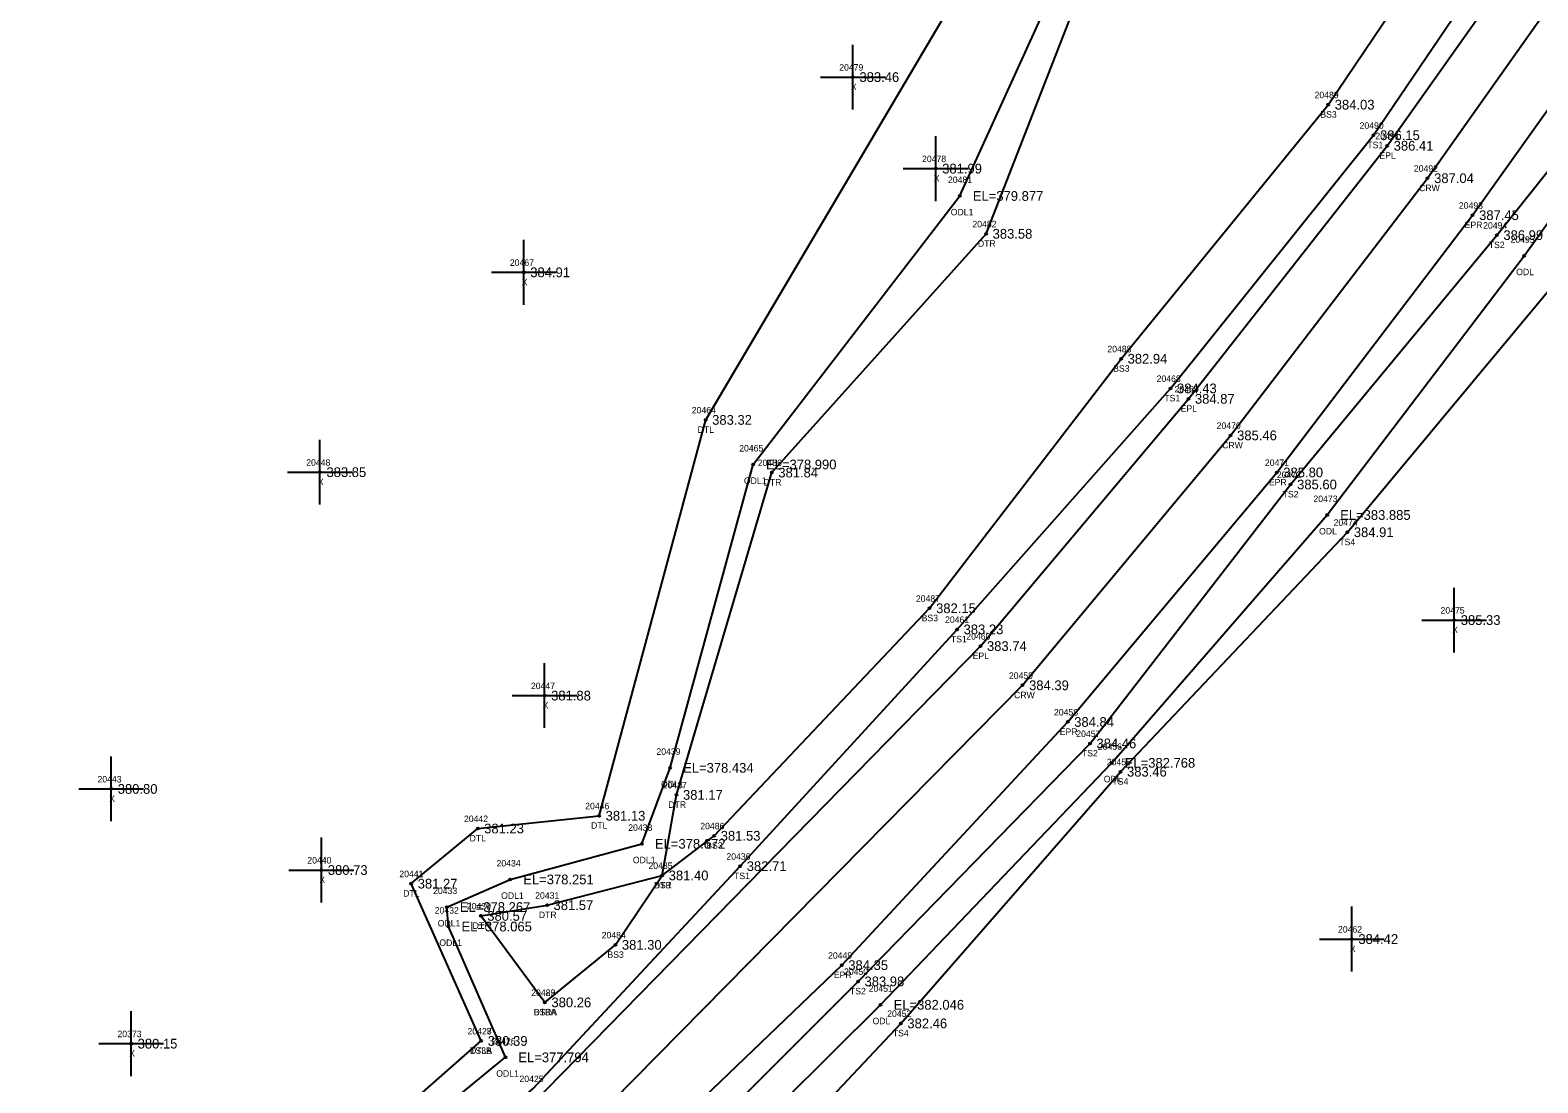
# Model space of a CAD drawing. Extents: x 2116373 to 2118139, y 979529 to 981026.
# Drawn here: x 2117652.3 to 2117884.9, y 980505.4 to 980667.9 of the extents above; entities that cross this region are included whole.
import ezdxf

# ---------------------------------------------------------------- set-up
doc = ezdxf.new("R2010")
doc.units = 0
for name, color, linetype in [('RD_DTM_BkLn1', 7, 'Continuous'), ('RD_DTM_BkLn2', 7, 'Continuous'), ('RD_DTM_BkLn_txCode', 7, 'Continuous'), ('RD_EX_H2O', 7, 'Continuous'), ('RD_EX_H2O_txCode', 7, 'Continuous'), ('RD_EX_Misc', 7, 'Continuous'), ('RD_EX_Misc_txCode', 7, 'Continuous'), ('RD_EX_Road', 7, 'Continuous'), ('RD_EX_Road_txCode', 7, 'Continuous'), ('RD_EX_TX_H2O_ELEV', 7, 'Continuous'), ('RD_EX_TX_Misc_ELEV', 7, 'Continuous'), ('RD_EX_TX_Road_ELEV', 7, 'Continuous'), ('RD_HC_Survey_ELEV', 7, 'Continuous'), ('RD_HC_Survey_txCode', 7, 'Continuous'), ('RD_SMD_Locator', 7, 'Continuous')]:
    doc.layers.add(name, color=color, linetype=linetype)

msp = doc.modelspace()

# ---------------------------------------------------------------- linework, layer by layer
at = {"layer": 'RD_DTM_BkLn1'}
msp.add_lwpolyline([(2117394.63, 980185.41), (2117475.35, 980259.39), (2117549.63, 980326.58), (2117623.5, 980394.2), (2117697.55, 980461.75), (2117735.02, 980495.39), (2117805.43, 980566.78), (2117837.53, 980605.36), (2117867.93, 980645.06), (2117897.09, 980686.34), (2117923.66, 980727.51), (2117948.72, 980771.39), (2117971.22, 980818.34), (2117988.96, 980866.05), (2117991.42, 980873.14), (2118004.26, 980915.09), (2118016.82, 980963.49), (2118028.02, 981013.26)], dxfattribs=at)
at = {"layer": 'RD_DTM_BkLn2'}
for points in [[(2117493.39, 980317.39), (2117496.3, 980311.64), (2117501.39, 980308.35), (2117540.21, 980337.44), (2117614.76, 980403.8), (2117689.51, 980469.61), (2117729.91, 980504.53), (2117761.86, 980538.86), (2117795.32, 980575.41), (2117828.25, 980612.61), (2117859.59, 980651.69), (2117887.1, 980692.35), (2117913.78, 980733.2), (2117937.24, 980777.08), (2117959.23, 980820.82), (2117978.84, 980869.89), (2117994.26, 980920.18), (2118007.51, 980964.57), (2118017.18, 981016.23)], [(2117731.72, 980517.83), (2117742.59, 980526.71), (2117749.81, 980537.43), (2117757.84, 980543.55), (2117791.08, 980578.67), (2117820.63, 980617.19), (2117852.6, 980656.41), (2117879.28, 980696.02), (2117905.09, 980736.34), (2117929.71, 980780.7), (2117946.34, 980825.73), (2117956.18, 980836.51)], [(2117403.18, 980177.15), (2117405.35, 980174.66), (2117487.26, 980245.43), (2117563.99, 980312.17), (2117634.65, 980381.46), (2117704.3, 980451.46), (2117722.65, 980465.11), (2117743.87, 980484.9), (2117780.03, 980521.07), (2117815.83, 980557.8), (2117846.79, 980597.78), (2117878.62, 980636.27), (2117911.26, 980677.34), (2117934.7, 980720.41), (2117959.82, 980759.29), (2117971.51, 980778.31), (2117986.8, 980774.26), (2117987.85, 980770.9), (2117995.22, 980745.17), (2118001.26, 980694.98), (2118008.4, 980640.04)], [(2117734.28, 980458.87), (2117786.65, 980514.59), (2117820.54, 980553.44), (2117855.54, 980590.41), (2117887.71, 980629.08), (2117918.16, 980671.7), (2117943.36, 980714.4), (2117971.9, 980758.61), (2117977.71, 980769.98), (2117980.03, 980767.32), (2117984.46, 980744.95), (2117988.75, 980693.43), (2117998.28, 980638.86)], [(2117660.7, 980455.28), (2117683.5, 980478.1), (2117721.89, 980511.88)]]:
    msp.add_lwpolyline(points, dxfattribs=at)
at = {"layer": 'RD_EX_H2O'}
for points in [[(2117721.89, 980511.88), (2117711.08, 980536.16), (2117721.34, 980544.67), (2117740.08, 980546.64), (2117756.52, 980607.75), (2117807.52, 980694.09), (2117832.51, 980780.02), (2117861.02, 980821.18)], [(2117660.7, 980455.28), (2117684.91, 980475.95), (2117725.61, 980509.35), (2117716.83, 980529.54), (2117716.58, 980532.55), (2117726.37, 980536.81), (2117746.69, 980542.31), (2117751.04, 980554.04), (2117763.83, 980600.87), (2117795.75, 980642.32), (2117816.16, 980687.22), (2117820.4, 980726.27), (2117839.5, 980777.36), (2117872.08, 980815.27)], [(2117731.72, 980517.83), (2117721.82, 980531.18), (2117732.04, 980532.84), (2117749.81, 980537.43), (2117752.02, 980549.86), (2117766.73, 980599.62), (2117799.8, 980636.48), (2117820.1, 980688.63), (2117829.93, 980722.05), (2117843.24, 980773.85), (2117874.6, 980813.55)], [(2117725.24, 980456.84), (2117729.88, 980462.23), (2117745.69, 980479.89), (2117783.52, 980517.46), (2117819.19, 980554.81), (2117852.43, 980593.07), (2117882.84, 980633.09), (2117913.27, 980675.65), (2117938.84, 980717.37), (2117963.41, 980761.5), (2117973.8, 980774.7), (2117982.58, 980769.22), (2117983.22, 980768.54), (2117990.51, 980745.52), (2117996.79, 980694.22), (2118004.21, 980639.35)]]:
    msp.add_lwpolyline(points, dxfattribs=at)
at = {"layer": 'RD_EX_Misc'}
for p, q in [((2117779.25, 980655.67), (2117779.25, 980665.67)), ((2117774.25, 980660.67), (2117784.25, 980660.67)), ((2117792.02, 980641.54), (2117792.02, 980651.54)), ((2117787.02, 980646.54), (2117797.02, 980646.54)), ((2117728.45, 980625.53), (2117728.45, 980635.53)), ((2117723.45, 980630.53), (2117733.45, 980630.53)), ((2117697, 980594.68), (2117697, 980604.68)), ((2117692, 980599.68), (2117702, 980599.68)), ((2117872.04, 980571.85), (2117872.04, 980581.85)), ((2117867.04, 980576.85), (2117877.04, 980576.85)), ((2117731.67, 980560.19), (2117731.67, 980570.19)), ((2117726.67, 980565.19), (2117736.67, 980565.19)), ((2117664.79, 980545.78), (2117664.79, 980555.78)), ((2117659.79, 980550.78), (2117669.79, 980550.78)), ((2117697.21, 980533.26), (2117697.21, 980543.26)), ((2117692.21, 980538.26), (2117702.21, 980538.26)), ((2117856.24, 980522.61), (2117856.24, 980532.61)), ((2117851.24, 980527.61), (2117861.24, 980527.61)), ((2117667.86, 980506.46), (2117667.86, 980516.46)), ((2117662.86, 980511.46), (2117672.86, 980511.46))]:
    msp.add_line(p, q, dxfattribs=at)
at = {"layer": 'RD_EX_Road'}
for points in [[(2117394.63, 980185.41), (2117388.45, 980192.75), (2117469.76, 980266.25), (2117487.02, 980282.1), (2117515.02, 980307.24), (2117543.53, 980333.04), (2117617.72, 980400.8), (2117691.88, 980468.07), (2117729.57, 980501.96), (2117798.93, 980572.83), (2117831.02, 980611), (2117861.69, 980650.07), (2117890.37, 980690.61), (2117916.67, 980731.93), (2117941.38, 980774.84), (2117963.75, 980821.95), (2117981.56, 980869.78), (2117996.2, 980917.73), (2118008.9, 980966.42), (2118019.55, 981015.46)], [(2117394.63, 980185.41), (2117401.85, 980177.36), (2117480.62, 980253.04), (2117556.27, 980319.95), (2117629.74, 980387.35), (2117703.2, 980454.29), (2117741.39, 980488.9), (2117777.53, 980523.58), (2117812.39, 980561.12), (2117844.66, 980599.64), (2117874.87, 980639.35), (2117904.78, 980681.4), (2117931.2, 980722.71), (2117957.05, 980767.35), (2117963.67, 980781.11), (2117980.28, 980814.62), (2117994.42, 980851.98)]]:
    msp.add_lwpolyline(points, dxfattribs=at)
at = {"layer": 'RD_SMD_Locator'}
for centre in [(2117779.25, 980660.67), (2117852.6, 980656.41), (2117859.59, 980651.69), (2117861.69, 980650.07), (2117792.02, 980646.54), (2117867.93, 980645.06), (2117795.75, 980642.32), (2117874.87, 980639.35), (2117799.8, 980636.48), (2117878.62, 980636.27), (2117882.84, 980633.09), (2117728.45, 980630.53), (2117820.63, 980617.19), (2117828.25, 980612.61), (2117831.02, 980611), (2117756.52, 980607.75), (2117837.53, 980605.36), (2117763.83, 980600.87), (2117697, 980599.68), (2117766.73, 980599.62), (2117844.66, 980599.64), (2117846.79, 980597.78), (2117852.43, 980593.07), (2117855.54, 980590.41), (2117791.08, 980578.67), (2117872.04, 980576.85), (2117795.32, 980575.41), (2117798.93, 980572.83), (2117731.67, 980565.19), (2117805.43, 980566.78), (2117812.39, 980561.12), (2117815.83, 980557.8), (2117751.04, 980554.04), (2117819.19, 980554.81), (2117820.54, 980553.44), (2117664.79, 980550.78), (2117752.02, 980549.86), (2117740.08, 980546.64), (2117721.34, 980544.67), (2117746.69, 980542.31), (2117757.84, 980543.55), (2117697.21, 980538.26), (2117749.81, 980537.43), (2117749.81, 980537.43), (2117761.86, 980538.86), (2117711.08, 980536.16), (2117726.37, 980536.81), (2117732.04, 980532.84), (2117716.58, 980532.55), (2117721.82, 980531.18), (2117716.83, 980529.54), (2117742.59, 980526.71), (2117856.24, 980527.61), (2117777.53, 980523.58), (2117780.03, 980521.07), (2117731.72, 980517.83), (2117731.72, 980517.83), (2117783.52, 980517.46), (2117786.65, 980514.59), (2117721.89, 980511.88), (2117721.89, 980511.88), (2117667.86, 980511.46), (2117725.61, 980509.35)]:
    msp.add_circle(centre, 0.15, dxfattribs=at)

# ---------------------------------------------------------------- texts
at = {"layer": 'RD_DTM_BkLn_txCode'}
for s, p in [('20489', (2117850.48, 980657.41)), ('BS3', (2117851.37, 980654.41)), ('20490', (2117857.43, 980652.69)), ('TS1', (2117858.63, 980649.69)), ('20494', (2117876.5, 980637.27)), ('TS2', (2117877.37, 980634.27)), ('20488', (2117818.51, 980618.19)), ('BS3', (2117819.4, 980615.19)), ('20468', (2117826.11, 980613.61)), ('TS1', (2117827.29, 980610.61)), ('20472', (2117844.67, 980598.78)), ('TS2', (2117845.55, 980595.78)), ('20474', (2117853.42, 980591.41)), ('TS4', (2117854.3, 980588.41)), ('20487', (2117788.96, 980579.67)), ('BS3', (2117789.85, 980576.67)), ('20461', (2117793.46, 980576.41)), ('TS1', (2117794.36, 980573.41)), ('20457', (2117813.71, 980558.8)), ('TS2', (2117814.59, 980555.8)), ('20455', (2117818.42, 980554.44)), ('TS4', (2117819.29, 980551.44)), ('20486', (2117755.69, 980544.55)), ('BS3', (2117756.61, 980541.55)), ('20436', (2117759.72, 980539.86)), ('20485', (2117747.69, 980538.43)), ('TS1', (2117760.9, 980536.86)), ('BS3', (2117748.58, 980535.43)), ('20484', (2117740.47, 980527.71)), ('BS3', (2117741.36, 980524.71)), ('20450', (2117777.87, 980522.07)), ('20483', (2117729.6, 980518.83)), ('TS2', (2117778.78, 980519.07)), ('BS3A', (2117730, 980515.83)), ('20452', (2117784.53, 980515.59)), ('20427', (2117719.77, 980512.88)), ('TS4', (2117785.4, 980512.59)), ('TS3B', (2117720.17, 980509.88)), ('20425', (2117727.79, 980505.53))]:
    msp.add_text(s, height=1, dxfattribs=at).set_placement(p)
at = {"layer": 'RD_EX_H2O_txCode'}
for s, p in [('20481', (2117793.91, 980644.32)), ('ODL1', (2117794.34, 980639.32)), ('20482', (2117797.68, 980637.48)), ('DTR', (2117798.53, 980634.48)), ('20495', (2117880.72, 980635.09)), ('ODL', (2117881.6, 980630.09)), ('20464', (2117754.38, 980608.75)), ('DTL', (2117755.27, 980605.75)), ('20465', (2117761.69, 980602.87)), ('20466', (2117764.56, 980600.62)), ('ODL1', (2117762.42, 980597.87)), ('DTR', (2117765.46, 980597.62)), ('20473', (2117850.31, 980595.07)), ('ODL', (2117851.18, 980590.07)), ('20439', (2117748.92, 980556.04)), ('20456', (2117817.05, 980556.81)), ('ODL1', (2117749.63, 980551.04)), ('20437', (2117749.9, 980550.86)), ('ODL', (2117817.95, 980551.81)), ('20446', (2117737.93, 980547.64)), ('DTR', (2117750.75, 980547.86)), ('20442', (2117719.22, 980545.67)), ('DTL', (2117738.83, 980544.64)), ('20438', (2117744.57, 980544.31)), ('DTL', (2117720.09, 980542.67)), ('20434', (2117724.25, 980538.81)), ('ODL1', (2117745.28, 980539.31)), ('20441', (2117709.25, 980537.16)), ('20435', (2117747.69, 980538.43)), ('DTL', (2117709.84, 980534.16)), ('20433', (2117714.46, 980534.55)), ('DTR', (2117748.54, 980535.43)), ('20430', (2117719.66, 980532.18)), ('ODL1', (2117724.96, 980533.81)), ('20431', (2117730.21, 980533.84)), ('20432', (2117714.71, 980531.54)), ('ODL1', (2117715.17, 980529.55)), ('DTR', (2117730.77, 980530.84)), ('DTR', (2117720.55, 980529.18)), ('ODL1', (2117715.42, 980526.54)), ('20429', (2117729.6, 980518.83)), ('20451', (2117781.68, 980519.46)), ('DTRA', (2117729.96, 980515.83)), ('ODL', (2117782.27, 980514.46)), ('20428', (2117719.77, 980512.88)), ('20426', (2117723.47, 980511.35)), ('DTLA', (2117720.16, 980509.88)), ('ODL1', (2117724.2, 980506.35))]:
    msp.add_text(s, height=1, dxfattribs=at).set_placement(p)
at = {"layer": 'RD_EX_Misc_txCode'}
for s, p in [('20479', (2117777.13, 980661.67)), ('X', (2117778.93, 980658.67)), ('20478', (2117789.91, 980647.54)), ('X', (2117791.71, 980644.54)), ('20467', (2117726.3, 980631.53)), ('X', (2117728.13, 980628.53)), ('20448', (2117694.88, 980600.68)), ('X', (2117696.68, 980597.68)), ('20475', (2117869.92, 980577.85)), ('X', (2117871.72, 980574.85)), ('20447', (2117729.55, 980566.19)), ('X', (2117731.36, 980563.19)), ('20443', (2117662.67, 980551.78)), ('X', (2117664.47, 980548.78)), ('20440', (2117695.05, 980539.26)), ('X', (2117696.9, 980536.26)), ('20462', (2117854.1, 980528.61)), ('X', (2117855.93, 980525.61)), ('20373', (2117665.75, 980512.46)), ('X', (2117667.55, 980509.46))]:
    msp.add_text(s, height=1, dxfattribs=at).set_placement(p)
at = {"layer": 'RD_EX_Road_txCode'}
for s, p in [('20491', (2117859.86, 980651.07)), ('EPL', (2117860.49, 980648.07)), ('20493', (2117872.75, 980640.35)), ('EPR', (2117873.64, 980637.35)), ('20469', (2117828.88, 980612)), ('EPL', (2117829.82, 980609)), ('20471', (2117842.82, 980600.64)), ('EPR', (2117843.43, 980597.64)), ('20460', (2117796.74, 980573.83)), ('EPL', (2117797.72, 980570.83)), ('20458', (2117810.27, 980562.12)), ('EPR', (2117811.16, 980559.12)), ('20449', (2117775.41, 980524.58)), ('EPR', (2117776.3, 980521.58))]:
    msp.add_text(s, height=1, dxfattribs=at).set_placement(p)
at = {"layer": 'RD_EX_TX_H2O_ELEV'}
for s, p in [('EL=379.877', (2117797.75, 980641.57)), ('383.58', (2117800.8, 980635.73)), ('383.32', (2117757.52, 980607)), ('EL=378.990', (2117765.83, 980600.12)), ('381.84', (2117767.73, 980598.87)), ('EL=383.885', (2117854.43, 980592.32)), ('EL=378.434', (2117753.04, 980553.29)), ('EL=382.768', (2117821.19, 980554.06)), ('381.17', (2117753.02, 980549.11)), ('381.13', (2117741.08, 980545.89)), ('381.23', (2117722.34, 980543.92)), ('EL=378.672', (2117748.69, 980541.56)), ('EL=378.251', (2117728.37, 980536.06)), ('381.40', (2117750.81, 980536.68)), ('381.27', (2117712.08, 980535.41)), ('EL=378.267', (2117718.58, 980531.8)), ('381.57', (2117733.04, 980532.09)), ('380.57', (2117722.82, 980530.43)), ('EL=378.065', (2117718.83, 980528.79)), ('380.26', (2117732.72, 980517.08)), ('EL=382.046', (2117785.52, 980516.71)), ('380.39', (2117722.89, 980511.13)), ('EL=377.794', (2117727.61, 980508.6))]:
    msp.add_text(s, height=1.5, dxfattribs=at).set_placement(p)
at = {"layer": 'RD_EX_TX_Misc_ELEV'}
for s, p in [('383.46', (2117780.25, 980659.92)), ('384.03', (2117853.6, 980655.66)), ('386.15', (2117860.59, 980650.94)), ('381.99', (2117793.02, 980645.79)), ('386.99', (2117879.62, 980635.52)), ('384.91', (2117729.45, 980629.78)), ('382.94', (2117821.63, 980616.44)), ('384.43', (2117829.25, 980611.86)), ('383.85', (2117698, 980598.93)), ('385.60', (2117847.79, 980597.03)), ('384.91', (2117856.54, 980589.66)), ('382.15', (2117792.08, 980577.92)), ('385.33', (2117873.04, 980576.1)), ('383.23', (2117796.32, 980574.66)), ('381.88', (2117732.67, 980564.44)), ('384.46', (2117816.83, 980557.05)), ('383.46', (2117821.54, 980552.69)), ('380.80', (2117665.79, 980550.03)), ('381.53', (2117758.84, 980542.8)), ('380.73', (2117698.21, 980537.51)), ('381.40', (2117750.81, 980536.68)), ('382.71', (2117762.86, 980538.11)), ('384.42', (2117857.24, 980526.86)), ('381.30', (2117743.59, 980525.96)), ('383.98', (2117781.03, 980520.32)), ('380.26', (2117732.72, 980517.08)), ('382.46', (2117787.65, 980513.84)), ('380.15', (2117668.86, 980510.71)), ('380.39', (2117722.89, 980511.13))]:
    msp.add_text(s, height=1.5, dxfattribs=at).set_placement(p)
at = {"layer": 'RD_EX_TX_Road_ELEV'}
for s, p in [('386.41', (2117862.69, 980649.32)), ('387.45', (2117875.87, 980638.6)), ('384.87', (2117832.02, 980610.25)), ('385.80', (2117845.66, 980598.89)), ('383.74', (2117799.93, 980572.08)), ('384.84', (2117813.39, 980560.37)), ('384.35', (2117778.53, 980522.83))]:
    msp.add_text(s, height=1.5, dxfattribs=at).set_placement(p)
at = {"layer": 'RD_HC_Survey_ELEV'}
for s, p in [('387.04', (2117868.93, 980644.31)), ('385.46', (2117838.53, 980604.61)), ('384.39', (2117806.43, 980566.03))]:
    msp.add_text(s, height=1.5, dxfattribs=at).set_placement(p)
at = {"layer": 'RD_HC_Survey_txCode'}
for s, p in [('20492', (2117865.81, 980646.06)), ('CRW', (2117866.61, 980643.06)), ('20470', (2117835.37, 980606.36)), ('CRW', (2117836.22, 980603.36)), ('20459', (2117803.31, 980567.78)), ('CRW', (2117804.11, 980564.78))]:
    msp.add_text(s, height=1, dxfattribs=at).set_placement(p)

doc.saveas('drawing.dxf')
